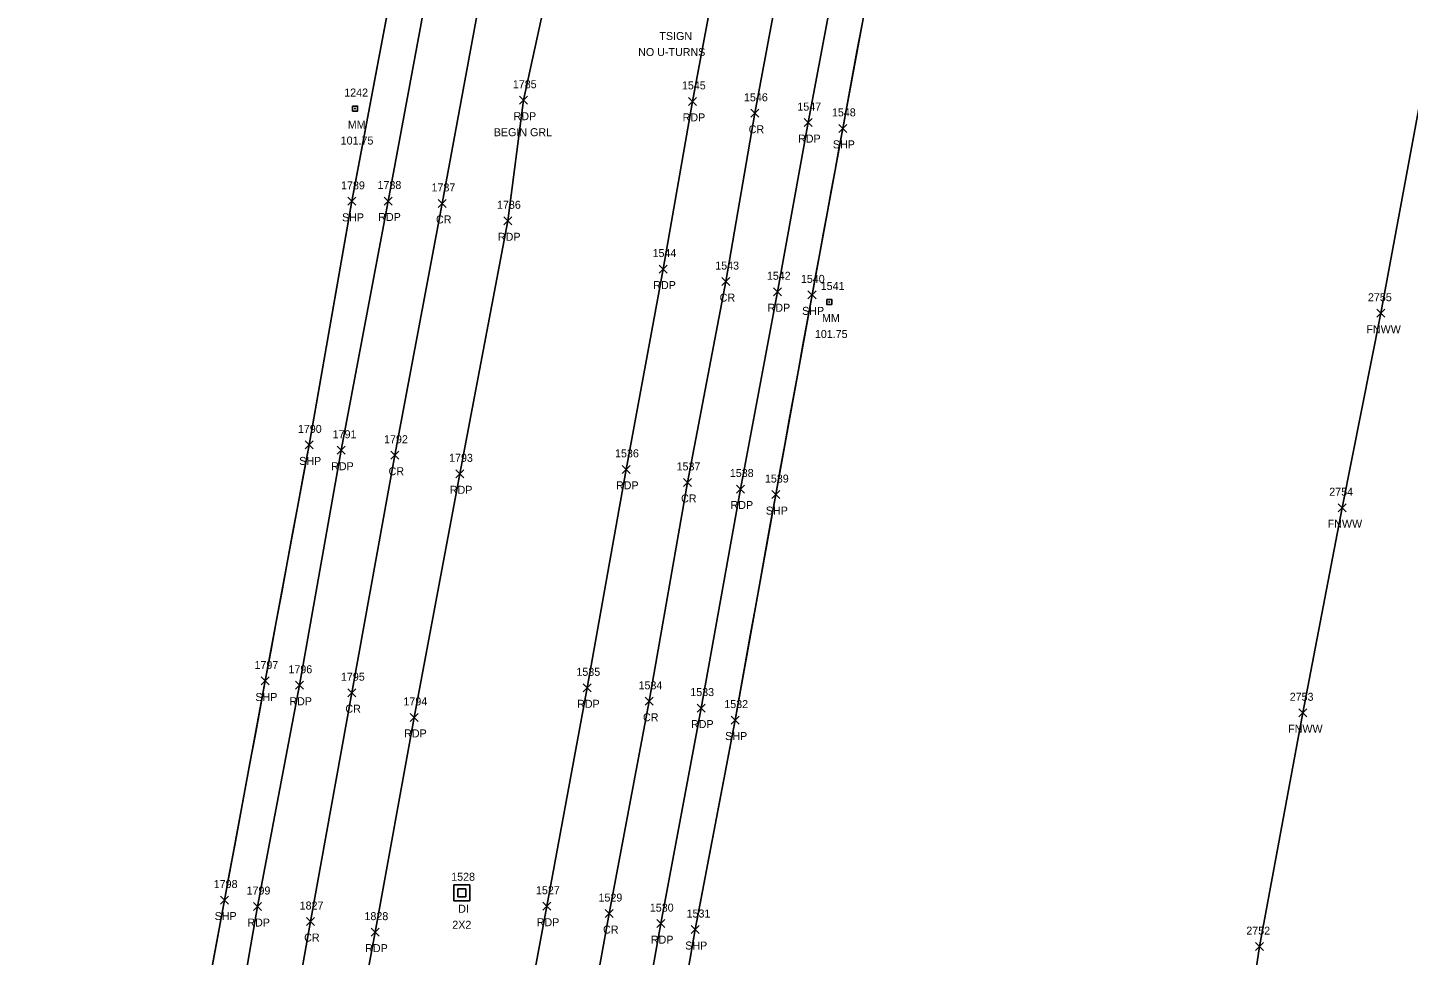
# Model space of a CAD drawing. Extents: x 1472022 to 1479249, y 777216 to 786527.
# Drawn here: x 1473646.9 to 1473992, y 780115.1 to 780347.1 of the extents above; entities that cross this region are included whole.
import ezdxf

# ---------------------------------------------------------------- set-up
doc = ezdxf.new("R2010")
doc.units = 0
for name, color, linetype in [('D_A', 7, 'Continuous'), ('D_C', 7, 'Continuous'), ('D_I', 7, 'Continuous'), ('DS', 7, 'Continuous'), ('L_A', 7, 'Continuous'), ('L_I', 7, 'Continuous'), ('L_TIC', 7, 'Continuous'), ('LFNC', 7, 'Continuous'), ('LSOGP', 7, 'Continuous'), ('P_A', 7, 'Continuous'), ('P_C', 7, 'Continuous'), ('P_I', 7, 'Continuous'), ('P_TIC', 7, 'Continuous'), ('PET', 7, 'Continuous'), ('PRC', 7, 'Continuous'), ('PSP', 7, 'Continuous'), ('S_A', 7, 'Continuous'), ('S_C', 7, 'Continuous'), ('S_I', 7, 'Continuous'), ('SRM', 7, 'Continuous')]:
    doc.layers.add(name, color=color, linetype=linetype)

msp = doc.modelspace()

# ---------------------------------------------------------------- linework, layer by layer
at = {"layer": 'DS'}
for p, q in [((1473753.47, 780132.79), (1473757.47, 780132.79)), ((1473753.47, 780128.79), (1473753.47, 780132.79)), ((1473754.47, 780129.79), (1473754.47, 780131.79)), ((1473754.47, 780131.79), (1473756.47, 780131.79)), ((1473756.47, 780131.79), (1473756.47, 780129.79)), ((1473757.47, 780132.79), (1473757.47, 780128.79)), ((1473757.47, 780128.79), (1473753.47, 780128.79)), ((1473756.47, 780129.79), (1473754.47, 780129.79)), ((1473755.47, 780130.79), (1473755.47, 780130.79)), ((1473755.47, 780130.79), (1473755.47, 780130.79))]:
    msp.add_line(p, q, dxfattribs=at)
at = {"layer": 'L_TIC'}
for points in [[(1473984.2, 780274.69), (1473986.2, 780276.69)], [(1473986.2, 780274.69), (1473984.2, 780276.69)], [(1473974.53, 780226.06), (1473976.53, 780228.06)], [(1473976.53, 780226.06), (1473974.53, 780228.06)], [(1473964.64, 780174.79), (1473966.64, 780176.79)], [(1473966.64, 780174.79), (1473964.64, 780176.79)], [(1473953.8, 780116.32), (1473955.8, 780118.32)], [(1473955.8, 780116.32), (1473953.8, 780118.32)]]:
    msp.add_lwpolyline(points, dxfattribs=at)
at = {"layer": 'LFNC'}
msp.add_lwpolyline([(1473875, 779673.99), (1473881.89, 779709.03), (1473887.76, 779743.71), (1473891.94, 779764.72), (1473898.61, 779803.9), (1473906.31, 779845.37), (1473911.16, 779870.48), (1473916.84, 779906.43), (1473925.6, 779951.14), (1473930.24, 779976.05), (1473935.19, 780005.03), (1473942.64, 780045), (1473949.23, 780080.08), (1473954.8, 780117.32), (1473965.64, 780175.79), (1473975.53, 780227.06), (1473985.2, 780275.69), (1474013.15, 780426.76), (1474027.53, 780457.02), (1474055.53, 780518.26), (1474067.56, 780545.19), (1474081.74, 780575.7)], dxfattribs=at)
at = {"layer": 'LSOGP'}
for points in [[(1473737.42, 780354.07), (1473735.84, 780345.67), (1473734.26, 780337.27), (1473732.69, 780328.87), (1473731.11, 780320.47), (1473729.53, 780312.07), (1473727.95, 780303.67), (1473726.61, 780296.05), (1473725.27, 780288.44), (1473723.93, 780280.83), (1473722.6, 780273.22), (1473721.26, 780265.61), (1473719.92, 780257.99), (1473718.58, 780250.38), (1473717.24, 780242.77), (1473715.87, 780235.39), (1473714.51, 780228.01), (1473713.14, 780220.63), (1473711.77, 780213.25), (1473710.41, 780205.87), (1473709.04, 780198.49), (1473707.67, 780191.11), (1473706.31, 780183.74), (1473705.03, 780176.89), (1473703.76, 780170.04), (1473702.48, 780163.2), (1473701.21, 780156.35), (1473699.94, 780149.51), (1473698.66, 780142.66), (1473697.39, 780135.82), (1473696.11, 780128.97), (1473694.6, 780120.88), (1473693.09, 780112.79)], [(1473812.49, 780114.35), (1473813.75, 780121.6), (1473814.99, 780128.14), (1473816.24, 780134.69), (1473817.49, 780141.24), (1473818.74, 780147.78), (1473819.99, 780154.33), (1473821.24, 780160.88), (1473822.49, 780167.42), (1473823.74, 780173.97), (1473825.01, 780181.02), (1473826.28, 780188.06), (1473827.55, 780195.11), (1473828.82, 780202.16), (1473830.09, 780209.21), (1473831.36, 780216.25), (1473832.63, 780223.3), (1473833.9, 780230.35), (1473835.03, 780236.59), (1473836.16, 780242.83), (1473837.3, 780249.07), (1473838.43, 780255.31), (1473839.57, 780261.55), (1473840.7, 780267.8), (1473841.83, 780274.04), (1473842.97, 780280.28), (1473843.93, 780285.48), (1473844.89, 780290.69), (1473845.85, 780295.89), (1473846.81, 780301.09), (1473847.77, 780306.3), (1473848.72, 780311.5), (1473849.68, 780316.71), (1473850.64, 780321.91), (1473851.83, 780328.32), (1473853.02, 780334.73), (1473854.21, 780341.14), (1473855.4, 780347.56)]]:
    msp.add_lwpolyline(points, dxfattribs=at)
at = {"layer": 'P_TIC'}
for points in [[(1473769.89, 780327.95), (1473771.89, 780329.95)], [(1473771.89, 780327.95), (1473769.89, 780329.95)], [(1473812.14, 780327.66), (1473814.14, 780329.66)], [(1473814.14, 780327.66), (1473812.14, 780329.66)], [(1473827.72, 780324.68), (1473829.72, 780326.68)], [(1473829.72, 780324.68), (1473827.72, 780326.68)], [(1473841, 780322.35), (1473843, 780324.35)], [(1473843, 780322.35), (1473841, 780324.35)], [(1473849.64, 780320.91), (1473851.64, 780322.91)], [(1473851.64, 780320.91), (1473849.64, 780322.91)], [(1473726.95, 780302.67), (1473728.95, 780304.67)], [(1473728.95, 780302.67), (1473726.95, 780304.67)], [(1473736.05, 780302.75), (1473738.05, 780304.75)], [(1473738.05, 780302.75), (1473736.05, 780304.75)], [(1473749.55, 780302.15), (1473751.55, 780304.15)], [(1473751.55, 780302.15), (1473749.55, 780304.15)], [(1473765.97, 780297.8), (1473767.97, 780299.8)], [(1473767.97, 780297.8), (1473765.97, 780299.8)], [(1473804.8, 780285.73), (1473806.8, 780287.73)], [(1473806.8, 780285.73), (1473804.8, 780287.73)], [(1473820.47, 780282.6), (1473822.47, 780284.6)], [(1473822.47, 780282.6), (1473820.47, 780284.6)], [(1473833.38, 780280.06), (1473835.38, 780282.06)], [(1473835.38, 780280.06), (1473833.38, 780282.06)], [(1473841.97, 780279.28), (1473843.97, 780281.28)], [(1473843.97, 780279.28), (1473841.97, 780281.28)], [(1473716.24, 780241.77), (1473718.24, 780243.77)], [(1473718.24, 780241.77), (1473716.24, 780243.77)], [(1473724.28, 780240.43), (1473726.28, 780242.43)], [(1473726.28, 780240.43), (1473724.28, 780242.43)], [(1473737.69, 780239.19), (1473739.69, 780241.19)], [(1473739.69, 780239.19), (1473737.69, 780241.19)], [(1473753.95, 780234.54), (1473755.95, 780236.54)], [(1473755.95, 780234.54), (1473753.95, 780236.54)], [(1473795.49, 780235.66), (1473797.49, 780237.66)], [(1473797.49, 780235.66), (1473795.49, 780237.66)], [(1473810.81, 780232.39), (1473812.81, 780234.39)], [(1473812.81, 780232.39), (1473810.81, 780234.39)], [(1473824.12, 780230.74), (1473826.12, 780232.74)], [(1473826.12, 780230.74), (1473824.12, 780232.74)], [(1473832.9, 780229.35), (1473834.9, 780231.35)], [(1473834.9, 780229.35), (1473832.9, 780231.35)], [(1473705.31, 780182.74), (1473707.31, 780184.74)], [(1473707.31, 780182.74), (1473705.31, 780184.74)], [(1473713.85, 780181.67), (1473715.85, 780183.67)], [(1473715.85, 780181.67), (1473713.85, 780183.67)], [(1473785.78, 780181.03), (1473787.78, 780183.03)], [(1473787.78, 780181.03), (1473785.78, 780183.03)], [(1473726.91, 780179.81), (1473728.91, 780181.81)], [(1473728.91, 780179.81), (1473726.91, 780181.81)], [(1473801.3, 780177.66), (1473803.3, 780179.66)], [(1473803.3, 780177.66), (1473801.3, 780179.66)], [(1473814.24, 780175.97), (1473816.24, 780177.97)], [(1473816.24, 780175.97), (1473814.24, 780177.97)], [(1473742.53, 780173.64), (1473744.53, 780175.64)], [(1473744.53, 780173.64), (1473742.53, 780175.64)], [(1473822.74, 780172.97), (1473824.74, 780174.97)], [(1473824.74, 780172.97), (1473822.74, 780174.97)], [(1473695.11, 780127.97), (1473697.11, 780129.97)], [(1473697.11, 780127.97), (1473695.11, 780129.97)], [(1473703.33, 780126.35), (1473705.33, 780128.35)], [(1473705.33, 780126.35), (1473703.33, 780128.35)], [(1473775.66, 780126.43), (1473777.66, 780128.43)], [(1473777.66, 780126.43), (1473775.66, 780128.43)], [(1473716.59, 780122.6), (1473718.59, 780124.6)], [(1473718.59, 780122.6), (1473716.59, 780124.6)], [(1473791.3, 780124.59), (1473793.3, 780126.59)], [(1473793.3, 780124.59), (1473791.3, 780126.59)], [(1473804.21, 780122.07), (1473806.21, 780124.07)], [(1473806.21, 780122.07), (1473804.21, 780124.07)], [(1473732.79, 780119.94), (1473734.79, 780121.94)], [(1473734.79, 780119.94), (1473732.79, 780121.94)], [(1473812.75, 780120.6), (1473814.75, 780122.6)], [(1473814.75, 780120.6), (1473812.75, 780122.6)]]:
    msp.add_lwpolyline(points, dxfattribs=at)
at = {"layer": 'PET'}
for points in [[(1473746.48, 779804.23), (1473735, 779806.45), (1473719.43, 779809.21), (1473722.68, 779826.96), (1473722.64, 779829.09), (1473731.65, 779877.71), (1473741.4, 779933.53), (1473746.83, 779966.3), (1473755, 780011.96), (1473766.14, 780070.64), (1473776.66, 780127.43), (1473786.78, 780182.03), (1473796.49, 780236.66), (1473805.8, 780286.73), (1473813.14, 780328.66), (1473818.03, 780354.99), (1473826.83, 780403.57), (1473832.05, 780432.32), (1473842.07, 780489.82), (1473851.78, 780539.26), (1473858.97, 780579.12), (1473867.36, 780624.13)], [(1473748.73, 779803.86), (1473746.48, 779804.23), (1473749.84, 779823.79), (1473758.54, 779869.63), (1473769.57, 779928.11), (1473775.61, 779960.49), (1473783.9, 780007.6), (1473794.95, 780065.64), (1473805.21, 780123.07), (1473815.24, 780176.97), (1473825.12, 780231.74), (1473834.38, 780281.06), (1473842, 780323.35), (1473851.32, 780373.06), (1473861.15, 780428.07), (1473871.31, 780483.08), (1473880.48, 780535.96), (1473887.71, 780574.3), (1473895.6, 780618.75)], [(1473794.13, 780615.24), (1473782.52, 780552.37), (1473771.2, 780492.12), (1473760.19, 780429.94), (1473749.17, 780369.33), (1473737.05, 780303.75), (1473725.28, 780241.43), (1473714.85, 780182.67), (1473704.33, 780127.35), (1473693.08, 780062.48), (1473683.1, 780008.62), (1473673.01, 779953.25), (1473663.96, 779903.08), (1473652.83, 779841.01), (1473649.09, 779823)], [(1473823.42, 780612.39), (1473811.33, 780545.89), (1473800.44, 780487.51), (1473789.09, 780424.89), (1473785.11, 780403.28), (1473778.08, 780362.23), (1473770.89, 780328.95), (1473766.97, 780298.8), (1473754.95, 780235.54), (1473743.53, 780174.64), (1473733.79, 780120.94), (1473722.51, 780060.44), (1473711.99, 780003.09), (1473701.81, 779948.07), (1473692.05, 779897.36), (1473680.21, 779836.9), (1473679.29, 779834.87), (1473676.24, 779818.18), (1473663.54, 779820.45), (1473649.09, 779823)]]:
    msp.add_lwpolyline(points, dxfattribs=at)
at = {"layer": 'PRC'}
for points in [[(1473735, 779806.45), (1473738.41, 779825.86), (1473746.88, 779873.78), (1473757.16, 779931.4), (1473763.53, 779963.46), (1473771.55, 780009.55), (1473781.83, 780068.07), (1473792.3, 780125.59), (1473802.3, 780178.66), (1473811.81, 780233.39), (1473821.47, 780283.6), (1473828.72, 780325.68), (1473837.7, 780374.01), (1473847.63, 780429.6), (1473858, 780486.03), (1473867.42, 780537.6), (1473874.56, 780576.61), (1473882.64, 780621.02)], [(1473807.59, 780614.57), (1473795.53, 780548.63), (1473784.81, 780489.97), (1473773.42, 780426.81), (1473762.25, 780366.77), (1473750.55, 780303.15), (1473738.69, 780240.19), (1473727.91, 780180.81), (1473717.59, 780123.6), (1473707.02, 780064.19), (1473696.41, 780006.24), (1473686.64, 779951.22), (1473677.2, 779900.33), (1473668.24, 779851.14), (1473663.54, 779820.45)]]:
    msp.add_lwpolyline(points, dxfattribs=at)
at = {"layer": 'PSP'}
for points in [[(1473748.73, 779803.86), (1473752.42, 779823.56), (1473762.71, 779868.4), (1473775.32, 779926.92), (1473782.16, 779958.6), (1473792.83, 780005.65), (1473803.68, 780063.67), (1473813.75, 780121.6), (1473823.74, 780173.97), (1473833.9, 780230.35), (1473842.97, 780280.28), (1473850.64, 780321.91), (1473860.15, 780373.2), (1473869.95, 780426.63), (1473880.31, 780480.63), (1473890.06, 780534.18), (1473897.21, 780573.03), (1473905.39, 780617.74)], [(1473785.49, 780617.45), (1473774.09, 780553.9), (1473763.03, 780493.85), (1473751.84, 780432.12), (1473740.58, 780370.87), (1473727.95, 780303.67), (1473717.24, 780242.77), (1473706.31, 780183.74), (1473696.11, 780128.97), (1473684.01, 780064.22), (1473674.48, 780009.55), (1473665.57, 779955.55), (1473658.15, 779904.32), (1473649.83, 779842.42), (1473650, 779841.1), (1473646.9, 779823.47)]]:
    msp.add_lwpolyline(points, dxfattribs=at)
at = {"layer": 'SRM'}
for points in [[(1473728.12, 780327.5), (1473729.37, 780327.5), (1473729.37, 780326.25), (1473728.12, 780326.25)], [(1473846.65, 780279.13), (1473847.9, 780279.13), (1473847.9, 780277.88), (1473846.65, 780277.88)]]:
    msp.add_lwpolyline(points, close=True, dxfattribs=at)
for centre in [(1473728.74, 780326.87), (1473847.28, 780278.5)]:
    msp.add_circle(centre, 0.0833, dxfattribs=at)

# ---------------------------------------------------------------- texts
at = {"layer": 'D_A'}
msp.add_text('DI', height=2, dxfattribs=at).set_placement((1473754.53, 780125.79))
at = {"layer": 'D_C'}
msp.add_text('2X2', height=2, dxfattribs=at).set_placement((1473753.05, 780121.79))
at = {"layer": 'D_I'}
msp.add_text('1528', height=2, dxfattribs=at).set_placement((1473752.78, 780133.79))
at = {"layer": 'L_A'}
for p in [(1473981.55, 780270.69), (1473971.88, 780222.06), (1473961.99, 780170.79)]:
    msp.add_text('FNWW', height=2, dxfattribs=at).set_placement(p)
at = {"layer": 'L_I'}
for s, p in [('2755', (1473981.94, 780278.69)), ('2754', (1473972.27, 780230.06)), ('2753', (1473962.38, 780178.79)), ('2752', (1473951.54, 780120.32))]:
    msp.add_text(s, height=2, dxfattribs=at).set_placement(p)
at = {"layer": 'P_A'}
for s, p in [('RDP', (1473768.38, 780323.95)), ('RDP', (1473810.63, 780323.66)), ('CR', (1473827.15, 780320.68)), ('RDP', (1473839.49, 780318.35)), ('SHP', (1473848.18, 780316.91)), ('SHP', (1473725.49, 780298.67)), ('RDP', (1473734.54, 780298.75)), ('CR', (1473748.98, 780298.15)), ('RDP', (1473764.46, 780293.8)), ('RDP', (1473803.29, 780281.73)), ('CR', (1473819.9, 780278.6)), ('RDP', (1473831.87, 780276.06)), ('SHP', (1473840.5, 780275.28)), ('SHP', (1473714.78, 780237.77)), ('RDP', (1473722.77, 780236.43)), ('CR', (1473737.13, 780235.19)), ('RDP', (1473752.44, 780230.54)), ('RDP', (1473793.97, 780231.66)), ('CR', (1473810.25, 780228.39)), ('RDP', (1473822.61, 780226.74)), ('SHP', (1473831.43, 780225.35)), ('SHP', (1473703.84, 780178.74)), ('RDP', (1473712.33, 780177.67)), ('CR', (1473726.34, 780175.81)), ('RDP', (1473784.26, 780177.03)), ('CR', (1473800.73, 780173.66)), ('RDP', (1473812.72, 780171.97)), ('RDP', (1473741.02, 780169.64)), ('SHP', (1473821.27, 780168.97)), ('SHP', (1473693.65, 780123.97)), ('RDP', (1473701.82, 780122.35)), ('RDP', (1473774.15, 780122.43)), ('CR', (1473716.03, 780118.6)), ('CR', (1473790.74, 780120.59)), ('RDP', (1473731.28, 780115.94)), ('RDP', (1473802.69, 780118.07)), ('SHP', (1473811.28, 780116.6))]:
    msp.add_text(s, height=2, dxfattribs=at).set_placement(p)
at = {"layer": 'P_C'}
msp.add_text('BEGIN GRL', height=2, dxfattribs=at).set_placement((1473763.42, 780319.95))
at = {"layer": 'P_I'}
for s, p in [('1785', (1473768.19, 780331.95)), ('1545', (1473810.45, 780331.66)), ('1546', (1473825.97, 780328.68)), ('1547', (1473839.31, 780326.35)), ('1548', (1473847.95, 780324.91)), ('1789', (1473725.25, 780306.67)), ('1788', (1473734.36, 780306.75)), ('1787', (1473747.86, 780306.15)), ('1786', (1473764.23, 780301.8)), ('1544', (1473803.11, 780289.73)), ('1543', (1473818.78, 780286.6)), ('1542', (1473831.69, 780284.06)), ('1540', (1473840.19, 780283.28)), ('1790', (1473714.46, 780245.77)), ('1791', (1473723.15, 780244.43)), ('1792', (1473736, 780243.19)), ('1536', (1473793.74, 780239.66)), ('1793', (1473752.25, 780238.54)), ('1537', (1473809.12, 780236.39)), ('1538', (1473822.43, 780234.74)), ('1539', (1473831.2, 780233.35)), ('1797', (1473703.61, 780186.74)), ('1796', (1473712.1, 780185.67)), ('1535', (1473784.08, 780185.03)), ('1795', (1473725.22, 780183.81)), ('1534', (1473799.61, 780181.66)), ('1794', (1473740.84, 780177.64)), ('1533', (1473812.54, 780179.97)), ('1532', (1473821.04, 780176.97)), ('1798', (1473693.42, 780131.97)), ('1799', (1473701.63, 780130.35)), ('1527', (1473773.97, 780130.43)), ('1827', (1473714.9, 780126.6)), ('1529', (1473789.6, 780128.59)), ('1530', (1473802.43, 780126.07)), ('1828', (1473731.1, 780123.94)), ('1531', (1473811.62, 780124.6))]:
    msp.add_text(s, height=2, dxfattribs=at).set_placement(p)
at = {"layer": 'S_A'}
for s, p in [('TSIGN', (1473804.82, 780344)), ('MM', (1473726.93, 780321.87)), ('MM', (1473845.47, 780273.5))]:
    msp.add_text(s, height=2, dxfattribs=at).set_placement(p)
at = {"layer": 'S_C'}
for s, p in [('NO U-TURNS', (1473799.52, 780340)), ('101.75', (1473725.15, 780317.87)), ('101.75', (1473843.69, 780269.5))]:
    msp.add_text(s, height=2, dxfattribs=at).set_placement(p)
at = {"layer": 'S_I'}
for s, p in [('1242', (1473726.05, 780329.87)), ('1541', (1473845.15, 780281.5))]:
    msp.add_text(s, height=2, dxfattribs=at).set_placement(p)

doc.saveas('drawing.dxf')
